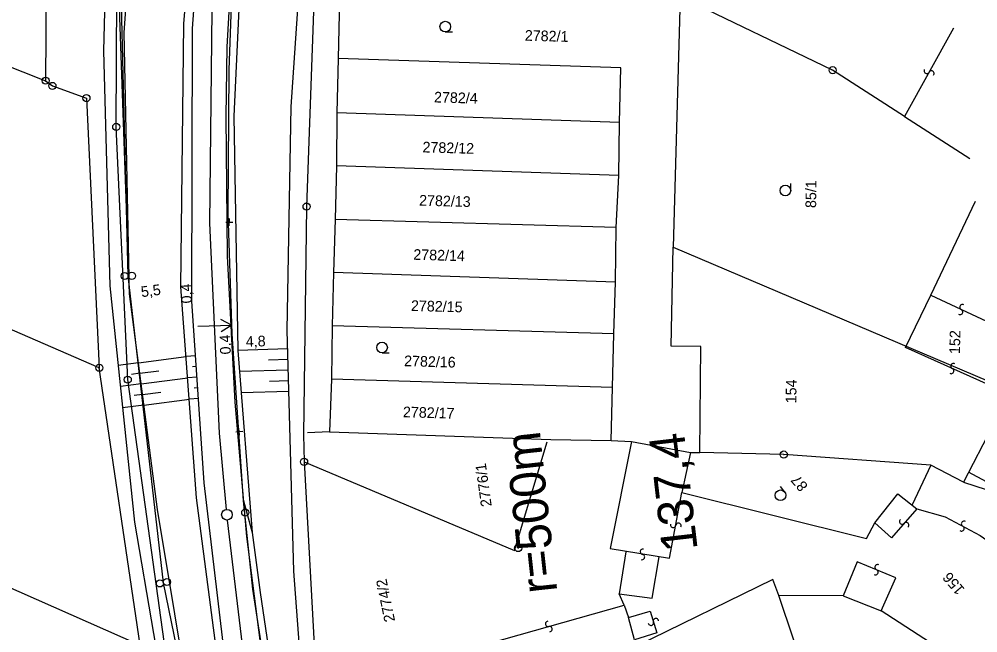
# Model space of a CAD drawing. Extents: x -658910 to -658078, y -1170373 to -1169331.
# Drawn here: x -658449.7 to -658315, y -1170123.2 to -1170036.9 of the extents above; entities that cross this region are included whole.
import ezdxf

# ---------------------------------------------------------------- set-up
doc = ezdxf.new("R2010")
doc.units = 0
for name, color, linetype in [('Vrstva 1', 7, 'Continuous'), ('Vrstva 10', 7, 'Continuous'), ('Vrstva 11', 7, 'Continuous'), ('Vrstva 12', 7, 'Continuous'), ('Vrstva 14', 7, 'Continuous'), ('Vrstva 26', 7, 'Continuous'), ('Vrstva 39', 7, 'Continuous'), ('Vrstva 6', 7, 'Continuous'), ('Vrstva 7', 7, 'Continuous'), ('Vrstva 8', 7, 'Continuous'), ('Vrstva 9', 7, 'Continuous')]:
    doc.layers.add(name, color=color, linetype=linetype)

msp = doc.modelspace()

# ---------------------------------------------------------------- linework, layer by layer
at = {"layer": 'Vrstva 1'}
for p, q in [((-658436.14, -1170052.059), (-658436.04, -1170052.059)), ((-658409.39, -1170063.27), (-658409.29, -1170063.27)), ((-658434.519, -1170087.609), (-658434.419, -1170087.609)), ((-658409.74, -1170099.17), (-658409.64, -1170099.17))]:
    msp.add_line(p, q, dxfattribs=at)
for points in [[(-658403.5, -1170214.23), (-658416.398, -1170174.469), (-658429.102, -1170126.129), (-658434.469, -1170087.609), (-658436.09, -1170052.059), (-658435.91, -1170014.719), (-658434.91, -1170000.301)], [(-658407.281, -1170000.499), (-658408.153, -1170029.241), (-658409.34, -1170063.27), (-658409.781, -1170095.35), (-658409.699, -1170099.11), (-658407.621, -1170136.909), (-658406.442, -1170153.331), (-658402.571, -1170171.88), (-658370.821, -1170208.971)]]:
    msp.add_lwpolyline(points, dxfattribs=at)
for centre in [(-658436.09, -1170052.059), (-658409.34, -1170063.27), (-658434.469, -1170087.609), (-658409.69, -1170099.17)]:
    msp.add_circle(centre, 0.499, dxfattribs=at)
at = {"layer": 'Vrstva 10'}
msp.add_line((-658421.421, -1170079.084), (-658419.831, -1170079.931), dxfattribs=at)
for points in [[(-658398.979, -1170189.297), (-658404.442, -1170166.563), (-658409.088, -1170142.051), (-658411.131, -1170114.565), (-658412.045, -1170080.658), (-658411.524, -1170049.223), (-658409, -1170012.742), (-658406.097, -1169985.499), (-658398.397, -1169958.238), (-658397.23, -1169955.206)], [(-658418.194, -1170104.631), (-658419.779, -1170081.152), (-658420.352, -1170064.135), (-658420.207, -1170044.041), (-658419.481, -1170023.386), (-658418.014, -1170007.481), (-658415.888, -1169988.253), (-658413.097, -1169969.872), (-658411.043, -1169959.49)], [(-658417.872, -1169961.611), (-658420.49, -1169976.06), (-658420.7, -1169976.84), (-658423.094, -1169993.471), (-658426.642, -1170037.568), (-658427.061, -1170074.546), (-658424.838, -1170104.223), (-658420.758, -1170135.42), (-658415.909, -1170162.863), (-658409.329, -1170190.564)], [(-658402.315, -1170190.348), (-658407.653, -1170169.771), (-658412.172, -1170148.826), (-658415.215, -1170129.375), (-658417.727, -1170109.679), (-658419.363, -1170090.792), (-658420.432, -1170070.237), (-658420.644, -1170050.611), (-658420.516, -1170040.788), (-658419.395, -1170021.018), (-658418.485, -1170009.912), (-658416.352, -1169990.562), (-658415.125, -1169981.811), (-658411.561, -1169961.716)], [(-658411.065, -1170191.125), (-658419.009, -1170162.093), (-658425.437, -1170135.194), (-658430.311, -1170105.886), (-658434.217, -1170075.522), (-658434.962, -1170038.771), (-658431.942, -1169996.387), (-658433.406, -1169990.734), (-658432.798, -1169972.528), (-658431.022, -1169965.688)], [(-658408.116, -1170190.76), (-658414.795, -1170162.084), (-658419.971, -1170133.751), (-658423.753, -1170102.123), (-658425.468, -1170076.574), (-658425.385, -1170038.217), (-658422.281, -1169996.311), (-658419.933, -1169977.592), (-658415.95, -1169967.863)], [(-658411.797, -1169969.902), (-658412.351, -1169971.115), (-658417.802, -1170012.345), (-658419.546, -1170050.542), (-658418.979, -1170083.49), (-658416.97, -1170109.116)], [(-658434.217, -1170075.522), (-658435.579, -1170036.672), (-658434.69, -1170005.528), (-658435.667, -1169999.009), (-658437.119, -1170012.108), (-658437.881, -1170041.388), (-658436.997, -1170074.409), (-658433.517, -1170107.658), (-658428.206, -1170138.963), (-658421.128, -1170167.236), (-658412.684, -1170191.854)], [(-658424.629, -1170080.093), (-658419.831, -1170079.931), (-658421.36, -1170080.883)], [(-658411.974, -1170083.301), (-658418.979, -1170083.49)], [(-658432.968, -1170085.231), (-658426.262, -1170084.369)], [(-658424.95, -1170084.281), (-658426.262, -1170084.369)], [(-658432.968, -1170085.231), (-658435.826, -1170085.599)], [(-658424.85, -1170085.778), (-658425.37, -1170085.813)], [(-658411.933, -1170084.8), (-658414.705, -1170084.875)], [(-658432.776, -1170086.719), (-658433.934, -1170086.868)], [(-658432.776, -1170086.719), (-658430.126, -1170086.378)], [(-658432.585, -1170088.207), (-658426.038, -1170087.365)], [(-658424.75, -1170087.274), (-658426.038, -1170087.361)], [(-658411.893, -1170086.3), (-658418.744, -1170086.484)], [(-658432.585, -1170088.207), (-658435.513, -1170088.583)], [(-658424.649, -1170088.771), (-658425.16, -1170088.805)], [(-658411.853, -1170087.799), (-658414.562, -1170087.872)], [(-658432.394, -1170089.695), (-658433.579, -1170089.847)], [(-658432.394, -1170089.695), (-658429.806, -1170089.362)], [(-658411.812, -1170089.299), (-658418.51, -1170089.479)], [(-658432.202, -1170091.183), (-658435.201, -1170091.568)], [(-658432.202, -1170091.183), (-658425.813, -1170090.361)], [(-658424.549, -1170090.268), (-658425.814, -1170090.353)], [(-658402.19, -1170190.341), (-658407.996, -1170166.975), (-658412.991, -1170142.221), (-658416.888, -1170117.058), (-658418.194, -1170104.631), (-658416.97, -1170109.116), (-658415.845, -1170117.564), (-658412.003, -1170143.514), (-658407.102, -1170167.433), (-658401.285, -1170189.676)]]:
    msp.add_lwpolyline(points, dxfattribs=at)
at = {"layer": 'Vrstva 12'}
for p, q in [((-658420.69, -1170065.452), (-658419.691, -1170065.463)), ((-658420.196, -1170065.957), (-658420.185, -1170064.958)), ((-658419.293, -1170094.971), (-658418.298, -1170094.866)), ((-658418.743, -1170095.416), (-658418.848, -1170094.421))]:
    msp.add_line(p, q, dxfattribs=at)
at = {"layer": 'Vrstva 14'}
msp.add_circle((-658417.958, -1170106.304), 0.5, dxfattribs=at)
at = {"layer": 'Vrstva 26'}
for points in [[(-658429.464, -1170116.165), (-658434.398, -1170073.025), (-658435.378, -1170033.046), (-658433.411, -1169996.615)], [(-658422.321, -1170150.908), (-658429.464, -1170116.165)]]:
    msp.add_lwpolyline(points, dxfattribs=at)
for centre in [(-658434.897, -1170073.037), (-658433.898, -1170073.012), (-658428.974, -1170116.064), (-658429.953, -1170116.265)]:
    msp.add_circle(centre, 0.5, dxfattribs=at)
at = {"layer": 'Vrstva 6'}
for points in [[(-658420.59, -1170105.878), (-658421.583, -1170095.123), (-658422.938, -1170065.589), (-658422.609, -1170035.66), (-658420.58, -1170006.923)], [(-658404.069, -1170193.255), (-658406.802, -1170183.303), (-658412.437, -1170159.296), (-658417.118, -1170133.524), (-658418.339, -1170124.958), (-658420.433, -1170107.363)]]:
    msp.add_lwpolyline(points, dxfattribs=at)
msp.add_circle((-658420.523, -1170106.609), 0.75, dxfattribs=at)
at = {"layer": 'Vrstva 8'}
for p, q in [((-658335.392, -1170044.139), (-658335.389, -1170044.04)), ((-658446.021, -1170045.619), (-658446.018, -1170045.52)), ((-658446.021, -1170045.619), (-658446.018, -1170045.52)), ((-658445.06, -1170046.35), (-658445.057, -1170046.251)), ((-658440.331, -1170048.02), (-658440.231, -1170048.02)), ((-658438.519, -1170085.941), (-658438.419, -1170085.941)), ((-658438.519, -1170085.941), (-658438.419, -1170085.941)), ((-658342.312, -1170098.141), (-658342.212, -1170098.141)), ((-658379.64, -1170111.301), (-658379.54, -1170111.301))]:
    msp.add_line(p, q, dxfattribs=at)
for points in [[(-658404, -1170000.27), (-658404.031, -1170004.18), (-658404.121, -1170011.66), (-658404.34, -1170019.121), (-658404.48, -1170026.609), (-658404.719, -1170033.99), (-658404.891, -1170042.461), (-658405.078, -1170050.08), (-658405.129, -1170057.539), (-658405.301, -1170065.09), (-658405.57, -1170072.531), (-658405.719, -1170080.031), (-658405.84, -1170087.559), (-658406.129, -1170094.961), (-658374.988, -1170096.02), (-658366.531, -1170096.18), (-658366.32, -1170088.719), (-658366.148, -1170081.16), (-658365.91, -1170073.9), (-658365.801, -1170066.211), (-658365.422, -1170058.879), (-658365.371, -1170051.43), (-658365.148, -1170043.74), (-658404.891, -1170042.461)], [(-658445.898, -1170026.1), (-658445.898, -1170026.1), (-658446.02, -1170045.57), (-658445.059, -1170046.301), (-658440.281, -1170048.02), (-658438.469, -1170085.941), (-658475.52, -1170069.85), (-658484.629, -1170065.83), (-658477.73, -1170053.32), (-658468.641, -1170036.621), (-658446.02, -1170045.57)], [(-658325.27, -1170050.609), (-658335.391, -1170044.09), (-658356.809, -1170033.711), (-658357.809, -1170068.961), (-658311.621, -1170088.621)], [(-658318.398, -1170038.16), (-658325.27, -1170050.609), (-658316.121, -1170056.51)], [(-658365.371, -1170051.43), (-658405.078, -1170050.08)], [(-658365.422, -1170058.879), (-658405.129, -1170057.539)], [(-658321.602, -1170075.75), (-658315.32, -1170062.52)], [(-658365.801, -1170066.211), (-658405.301, -1170065.09)], [(-658317.02, -1170102.02), (-658321.602, -1170099.621), (-658342.262, -1170098.141), (-658354.07, -1170097.871), (-658353.922, -1170082.941), (-658358.102, -1170082.92), (-658357.809, -1170068.961)], [(-658365.91, -1170073.9), (-658405.57, -1170072.531)], [(-658312, -1170089), (-658325.148, -1170083.109), (-658321.602, -1170075.75), (-658313.039, -1170079.73)], [(-658366.148, -1170081.16), (-658405.719, -1170080.031)], [(-658483.512, -1170102.52), (-658432.73, -1170124.961), (-658438.469, -1170085.941)], [(-658366.32, -1170088.719), (-658405.84, -1170087.559)], [(-658311.539, -1170091.51), (-658317.02, -1170102.02), (-658312.238, -1170103.58), (-658309.59, -1170105.5)], [(-658406.129, -1170094.961), (-658409.23, -1170095.07)], [(-658409.69, -1170099.17), (-658380.132, -1170111.641), (-658375.53, -1170096.36)], [(-658363.648, -1170096.33), (-658366.672, -1170111.379), (-658358.301, -1170112.73), (-658356.57, -1170103.48)], [(-658366.531, -1170096.18), (-658363.648, -1170096.33), (-658355.359, -1170097.871), (-658354.07, -1170097.871)], [(-658355.359, -1170097.871), (-658356.57, -1170103.48), (-658330.621, -1170109.941), (-658329.48, -1170107.77), (-658326.219, -1170103.68), (-658323.559, -1170105.76), (-658327.129, -1170109.871), (-658329.48, -1170107.77)], [(-658321.602, -1170099.621), (-658324.219, -1170105.219)], [(-658309.32, -1170104.359), (-658316.301, -1170100.629)], [(-658323.559, -1170105.76), (-658319.559, -1170106.891), (-658314.66, -1170109.539), (-658307.531, -1170114.5)], [(-658364.48, -1170111.809), (-658365.398, -1170117.73), (-658360.762, -1170118.32), (-658359.789, -1170112.539)], [(-658320.859, -1170125.121), (-658328.59, -1170120.141), (-658326.5, -1170115.461), (-658331.949, -1170113.211), (-658333.93, -1170118), (-658342.941, -1170117.961), (-658343.781, -1170115.711), (-658362.941, -1170125.1)], [(-658364.672, -1170119.32), (-658365.398, -1170117.73)], [(-658332.82, -1170144.281), (-658334.559, -1170142.949), (-658342.941, -1170117.961)], [(-658333.93, -1170118), (-658328.59, -1170120.141)], [(-658385.91, -1170125.309), (-658364.672, -1170119.32), (-658364.109, -1170121.039), (-658361.059, -1170120.18), (-658360.109, -1170123.199), (-658363.262, -1170124.211), (-658364.109, -1170121.039)]]:
    msp.add_lwpolyline(points, dxfattribs=at)
for centre in [(-658335.391, -1170044.09), (-658446.02, -1170045.57), (-658446.02, -1170045.57), (-658445.059, -1170046.301), (-658440.281, -1170048.02), (-658438.469, -1170085.941), (-658438.469, -1170085.941), (-658342.262, -1170098.141), (-658379.59, -1170111.301)]:
    msp.add_circle(centre, 0.499, dxfattribs=at)
for centre, radius, start, end in [((-658322.155, -1170044.193), 0.376, 144.12479, 330.43592), ((-658321.498, -1170044.561), 0.377, 323.44875, 151.11196), ((-658317.478, -1170078.081), 0.377, 237.4021, 65.06532), ((-658317.157, -1170077.4), 0.376, 58.07814, 244.38928), ((-658318.732, -1170086.394), 0.377, 238.2216, 65.88482), ((-658318.42, -1170085.709), 0.376, 58.89764, 245.20878), ((-658325.621, -1170107.558), 0.376, 132.04153, 318.35266), ((-658316.926, -1170107.881), 0.376, 54.66985, 240.98098), ((-658357.81, -1170108.035), 0.376, 162.43199, 348.74313), ((-658357.07, -1170108.178), 0.377, 341.75595, 169.41917), ((-658325.055, -1170108.056), 0.377, 311.36549, 139.0287), ((-658317.287, -1170108.542), 0.377, 233.99381, 61.65702), ((-658362.066, -1170111.808), 0.376, 74.18049, 260.49162), ((-658362.186, -1170112.552), 0.377, 253.50445, 81.16766), ((-658329.374, -1170114.687), 0.377, 239.83391, 67.49712), ((-658329.081, -1170113.993), 0.376, 60.50995, 246.82108), ((-658375.386, -1170121.956), 0.376, 98.77363, 285.08477), ((-658375.186, -1170122.682), 0.377, 278.09759, 105.76081), ((-658360.95, -1170121.799), 0.376, 190.42448, 16.73561), ((-658360.23, -1170121.578), 0.377, 9.74844, 197.41165)]:
    msp.add_arc(centre, radius, start, end, dxfattribs=at)
at = {"layer": 'Vrstva 9'}
for p, q in [((-658389.84, -1170038.711), (-658388.84, -1170038.711)), ((-658341.287, -1170061.02), (-658341.273, -1170060.021)), ((-658398.73, -1170083.84), (-658397.73, -1170083.84)), ((-658342.128, -1170103.419), (-658342.739, -1170102.628))]:
    msp.add_line(p, q, dxfattribs=at)
for centre in [(-658389.84, -1170037.961), (-658342.037, -1170061.01), (-658398.73, -1170083.09), (-658342.722, -1170103.878)]:
    msp.add_circle(centre, 0.75, dxfattribs=at)

# ---------------------------------------------------------------- texts
at = {"layer": 'Vrstva 11'}
for s, rotation, p in [('5,5', 7.33025, (-658432.52, -1170076.02)), ('0,4', 92.82313, (-658425.439, -1170076.855)), ('0,4', 91.92848, (-658419.983, -1170084.04)), ('4,8', 1.54504, (-658417.863, -1170082.996))]:
    msp.add_text(s, height=1.5, rotation=rotation, dxfattribs=at).set_placement(p)
at = {"layer": 'Vrstva 39'}
msp.add_text('r=500m', height=4.999, rotation=96.20677, dxfattribs=at).set_placement((-658374.091, -1170117.403))
at = {"layer": 'Vrstva 7'}
msp.add_text('137,4', height=4.999, rotation=96.63196, dxfattribs=at).set_placement((-658354.353, -1170111.501))
at = {"layer": 'Vrstva 9'}
for s, rotation, p in [('2782/1', 358.35453, (-658378.68, -1170039.941)), ('2782/4', 358.35453, (-658391.441, -1170048.621)), ('2782/12', 358.35453, (-658393.059, -1170055.65)), ('85/1', 89.18568, (-658337.718, -1170063.486)), ('2782/13', 358.35453, (-658393.539, -1170063.129)), ('2782/14', 358.35453, (-658394.352, -1170070.75)), ('2782/15', 358.35453, (-658394.68, -1170077.941)), ('152', 88.72663, (-658317.5, -1170084.02)), ('2782/16', 358.35453, (-658395.648, -1170085.711)), ('154', 89.18568, (-658340.501, -1170090.947)), ('2782/17', 358.35453, (-658395.809, -1170092.891)), ('2776/1', 97.91147, (-658383.308, -1170105.372)), ('87', 130.49568, (-658338.778, -1170102.543)), ('2774/2', 101.61262, (-658396.885, -1170121.53)), ('156', 130.49568, (-658316.744, -1170117.082))]:
    msp.add_text(s, height=1.5, rotation=rotation, dxfattribs=at).set_placement(p)

doc.saveas('drawing.dxf')
